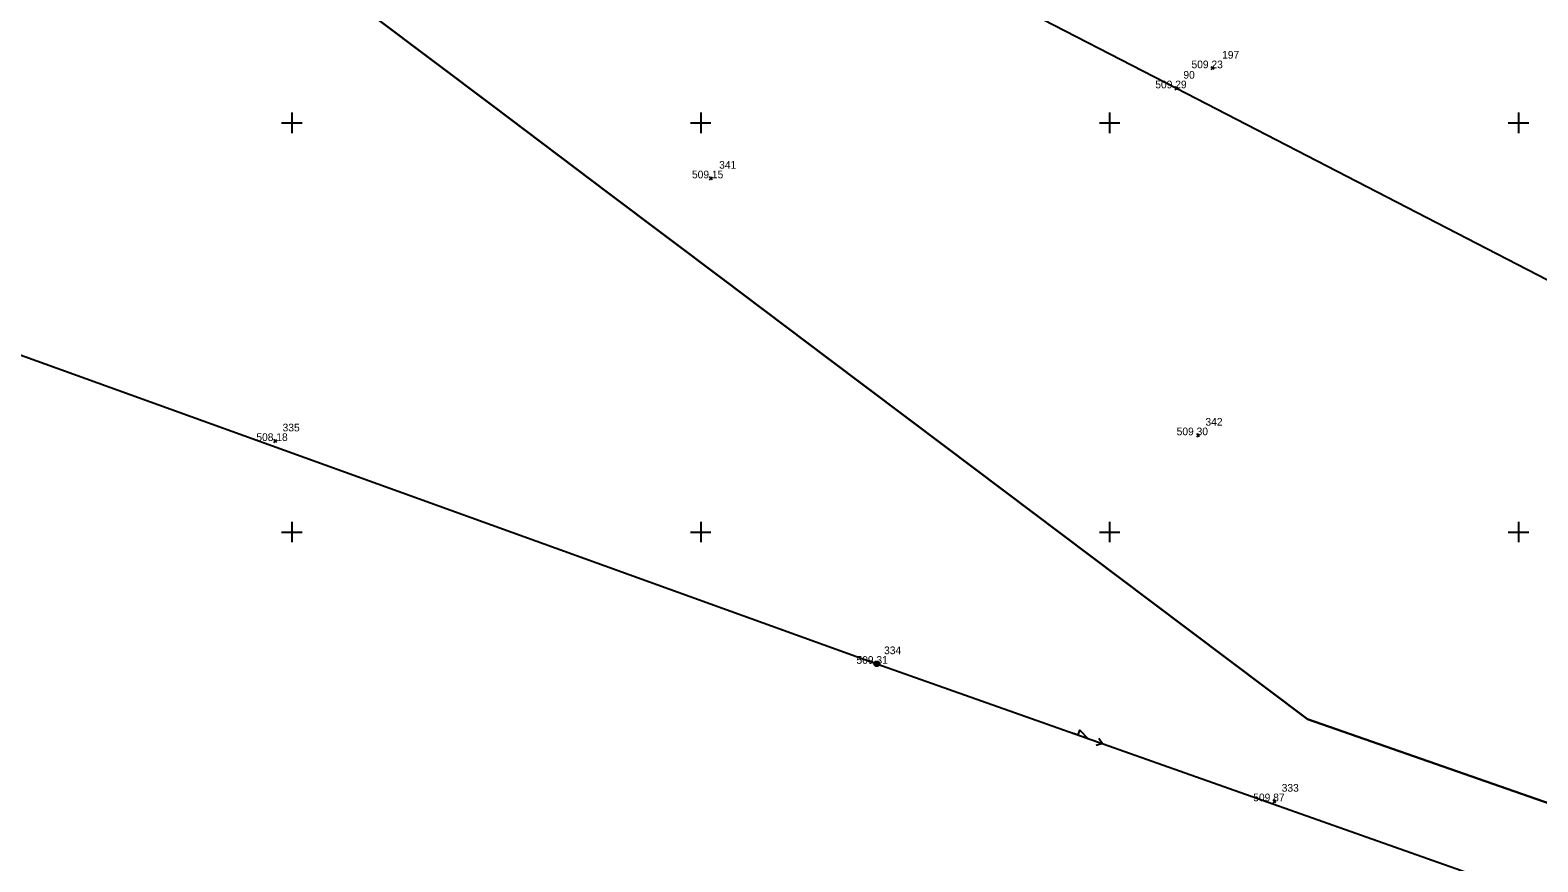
# Model space of a CAD drawing. Extents: x -408550 to -407654, y -1233019 to -1231230.
# Drawn here: x -408112.8 to -408039.1, y -1232076.1 to -1232035.5 of the extents above; entities that cross this region are included whole.
import ezdxf

# ---------------------------------------------------------------- set-up
doc = ezdxf.new("R2010")
doc.units = 0
for name, color, linetype in [('Level 1', 7, 'Continuous'), ('Level 12', 7, 'Continuous'), ('Level 22', 7, 'Continuous'), ('Level 23', 7, 'Continuous'), ('Level 25', 7, 'Continuous'), ('Level 26', 7, 'Continuous'), ('Level 4', 7, 'Continuous'), ('Level 40', 7, 'Continuous'), ('Level 45', 7, 'Continuous')]:
    doc.layers.add(name, color=color, linetype=linetype)

msp = doc.modelspace()

# ---------------------------------------------------------------- linework, layer by layer
at = {"layer": 'Level 1'}
for p, q in [((-408100, -1232039.5), (-408100, -1232040.5)), ((-408080, -1232039.5), (-408080, -1232040.5)), ((-408060, -1232039.5), (-408060, -1232040.5)), ((-408040, -1232039.5), (-408040, -1232040.5)), ((-408100.5, -1232040), (-408099.5, -1232040)), ((-408080.5, -1232040), (-408079.5, -1232040)), ((-408060.5, -1232040), (-408059.5, -1232040)), ((-408040.5, -1232040), (-408039.5, -1232040)), ((-408100, -1232059.5), (-408100, -1232060.5)), ((-408080, -1232059.5), (-408080, -1232060.5)), ((-408060, -1232059.5), (-408060, -1232060.5)), ((-408040, -1232059.5), (-408040, -1232060.5)), ((-408100.5, -1232060), (-408099.5, -1232060)), ((-408080.5, -1232060), (-408079.5, -1232060)), ((-408060.5, -1232060), (-408059.5, -1232060)), ((-408040.5, -1232060), (-408039.5, -1232060))]:
    msp.add_line(p, q, dxfattribs=at)
for points in [[(-408035.27, -1232074.4), (-408044.77, -1232071.09), (-408050.33, -1232069.15), (-408058.02, -1232063.36), (-408068.11, -1232055.77), (-408073.77, -1232051.51), (-408078.94, -1232047.62), (-408084.51, -1232043.43), (-408090.17, -1232039.17), (-408096, -1232034.78), (-408102.42, -1232029.95), (-408115.87, -1232019.83), (-408127.68, -1232010.95), (-408125.76, -1232010.23), (-408100.15, -1231999.15), (-408086.61, -1231994.04), (-408066.68, -1231985.23), (-408038.79, -1231974.16)], [(-408165.18, -1232022.99), (-408146.37, -1232017.08), (-408133.36, -1232013.08), (-408127.68, -1232010.95), (-408115.87, -1232019.83), (-408102.42, -1232029.95), (-408096, -1232034.78), (-408090.17, -1232039.17), (-408084.51, -1232043.43), (-408078.94, -1232047.62), (-408073.77, -1232051.51), (-408068.11, -1232055.77), (-408058.02, -1232063.36), (-408050.33, -1232069.15), (-408044.77, -1232071.09), (-408035.27, -1232074.4)]]:
    msp.add_lwpolyline(points, dxfattribs=at)
at = {"layer": 'Level 12'}
msp.add_lwpolyline([(-408037.34, -1231968.54), (-408046.88, -1231972.68), (-408058.05, -1231977.49), (-408065.95, -1231981.2), (-408066.72, -1231981.53), (-408081.67, -1231987.81), (-408090.6, -1231991.55), (-408110.81, -1232000.25), (-408118.15, -1232003.47), (-408117.7, -1232004.22), (-408114.75, -1232007.99), (-408081.23, -1232025.67), (-408056.73, -1232038.31), (-408035.18, -1232049.43)], dxfattribs=at)
at = {"layer": 'Level 22'}
msp.add_lwpolyline([(-408151.19, -1232037.68), (-408071.39, -1232066.44), (-407993.81, -1232093.84), (-407921.31, -1232119.76), (-407919.17, -1232112.74), (-407917.389, -1232106.855)], dxfattribs=at)
at = {"layer": 'Level 23'}
for points in [[(-408054.891, -1232037.399), (-408055.029, -1232037.261)], [(-408055.029, -1232037.399), (-408054.891, -1232037.261)], [(-408056.661, -1232038.379), (-408056.799, -1232038.241)], [(-408056.799, -1232038.379), (-408056.661, -1232038.241)], [(-408079.431, -1232042.779), (-408079.569, -1232042.641)], [(-408079.569, -1232042.779), (-408079.431, -1232042.641)], [(-408100.741, -1232055.619), (-408100.879, -1232055.481)], [(-408100.879, -1232055.619), (-408100.741, -1232055.481)], [(-408055.601, -1232055.339), (-408055.739, -1232055.201)], [(-408055.739, -1232055.339), (-408055.601, -1232055.201)], [(-408071.321, -1232066.509), (-408071.459, -1232066.371)], [(-408071.459, -1232066.509), (-408071.321, -1232066.371)], [(-408051.871, -1232073.229), (-408052.009, -1232073.091)], [(-408052.009, -1232073.229), (-408051.871, -1232073.091)]]:
    msp.add_lwpolyline(points, dxfattribs=at)
at = {"layer": 'Level 25'}
for points in [[(-408061.771, -1232069.837), (-408061.535, -1232069.92), (-408061.452, -1232069.684), (-408061.063, -1232070.086), (-408060.356, -1232070.336)], [(-408060.529, -1232070.076), (-408060.356, -1232070.336), (-408060.654, -1232070.429)]]:
    msp.add_lwpolyline(points, dxfattribs=at)
at = {"layer": 'Level 4'}
msp.add_lwpolyline([(-408035.27, -1232074.4), (-408044.77, -1232071.09), (-408050.33, -1232069.15), (-408058.02, -1232063.36), (-408068.11, -1232055.77), (-408073.77, -1232051.51), (-408078.94, -1232047.62), (-408084.51, -1232043.43), (-408090.17, -1232039.17), (-408096, -1232034.78), (-408102.42, -1232029.95), (-408115.87, -1232019.83), (-408127.68, -1232010.95), (-408125.76, -1232010.23), (-408100.15, -1231999.15), (-408086.61, -1231994.04), (-408066.68, -1231985.23), (-408038.79, -1231974.16)], dxfattribs=at)
at = {"layer": 'Level 45'}
msp.add_lwpolyline([(-408071.429, -1232066.321), (-408071.351, -1232066.321), (-408071.289, -1232066.366), (-408071.265, -1232066.44), (-408071.289, -1232066.514), (-408071.351, -1232066.559), (-408071.429, -1232066.559), (-408071.491, -1232066.514), (-408071.515, -1232066.44), (-408071.491, -1232066.366), (-408071.429, -1232066.321), (-408071.42, -1232066.33), (-408071.36, -1232066.33), (-408071.32, -1232066.35), (-408071.46, -1232066.35), (-408071.48, -1232066.37), (-408071.3, -1232066.37), (-408071.3, -1232066.39), (-408071.48, -1232066.39), (-408071.49, -1232066.41), (-408071.29, -1232066.41), (-408071.28, -1232066.43), (-408071.5, -1232066.43), (-408071.5, -1232066.45), (-408071.28, -1232066.45), (-408071.288, -1232066.47), (-408071.491, -1232066.47), (-408071.49, -1232066.49), (-408071.288, -1232066.49), (-408071.3, -1232066.51), (-408071.48, -1232066.51), (-408071.46, -1232066.53), (-408071.32, -1232066.53), (-408071.347, -1232066.55), (-408071.432, -1232066.55)], dxfattribs=at)

# ---------------------------------------------------------------- texts
at = {"layer": 'Level 26'}
for s, p in [('197', (-408054.499, -1232036.86)), ('90', (-408056.393, -1232037.84)), ('341', (-408079.099, -1232042.24)), ('342', (-408055.314, -1232054.8)), ('335', (-408100.454, -1232055.08)), ('334', (-408071.034, -1232065.97)), ('333', (-408051.584, -1232072.69))]:
    msp.add_text(s, height=0.375, dxfattribs=at).set_placement(p)
at = {"layer": 'Level 40'}
for s, p in [('509 23', (-408055.997, -1232037.33)), ('509 29', (-408057.768, -1232038.31)), ('509 15', (-408080.431, -1232042.71)), ('508 18', (-408101.738, -1232055.55)), ('509 30', (-408056.723, -1232055.27)), ('509 31', (-408072.383, -1232066.44)), ('509 87', (-408052.977, -1232073.16))]:
    msp.add_text(s, height=0.375, dxfattribs=at).set_placement(p)

doc.saveas('drawing.dxf')
